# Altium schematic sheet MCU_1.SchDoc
size A4; PageSetup: Record=PageOptions|CenterHorizontal=True|CenterVertical=True|PrintScale=0.98|XCorrection=1.00|YCorrection=1.00|PrintKind=0|BorderSize=5000000|LeftOffset=0|BottomOffset=0|Orientation=2|PaperLength=1000|PaperWidth=1000|Scale=100|PaperSource=7|PrintQuality=-4|MediaType=1|DitherType=10|PaperKind=A4 210x297 ºÁÃ×|PrintScaleMode=1
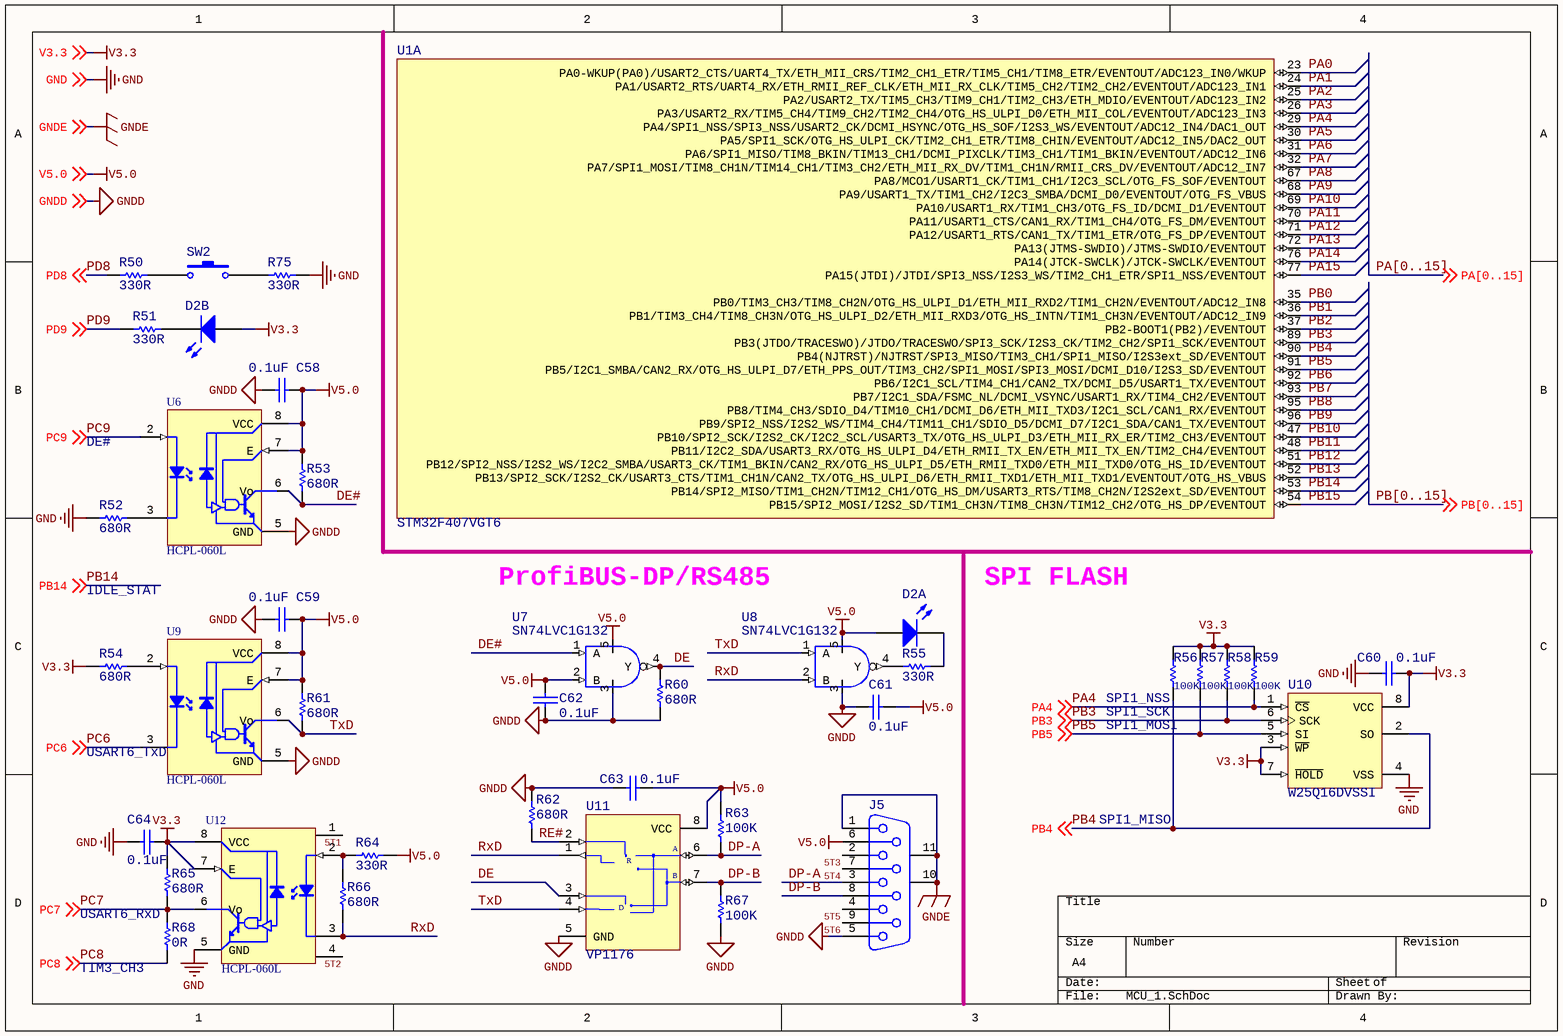
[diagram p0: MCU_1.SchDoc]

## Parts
C58  0.1uF  [C1608(0603)]
C59  0.1uF  [C1608(0603)]
C60  0.1uF  [C1608(0603)]
C61  0.1uF  [C1608(0603)]
C62  0.1uF  [C1608(0603)]
C63  0.1uF  [C1608(0603)]
C64  0.1uF  [C1608(0603)]
D2  LED-2  [LED-2]  (value not drawn)  (parts A,B of 2)
J5  D Connector 9  [DB9F]  (value not drawn)
R50  330R  [R1608(0603)]
R51  330R  [R1608(0603)]
R52  680R  [R1608(0603)]
R53  680R  [R1608(0603)]
R54  680R  [R1608(0603)]
R55  330R  [R1608(0603)]
R56  100K  [R1608(0603)]
R57  100K  [R1608(0603)]
R58  100K  [R1608(0603)]
R59  100K  [R1608(0603)]
R60  680R  [R1608(0603)]
R61  680R  [R1608(0603)]
R62  680R  [R1608(0603)]
R63  100K  [R1608(0603)]
R64  330R  [R1608(0603)]
R65  680R  [R1608(0603)]
R66  680R  [R1608(0603)]
R67  100K  [R1608(0603)]
R68  0R  [R1608(0603)]
R75  330R  [R1608(0603)]
SW2  SW-PB  [KEY 4.5x4.5x4.3mm]  (value not drawn)
U1  STM32F407VGT6  [TQFP100_N]  (part A of 5)
U6  HCPL-060L  [SO8_M]
U7  SN74LVC1G132  [SOT23-5_N]
U8  SN74LVC1G132  [SOT23-5_N]
U9  HCPL-060L  [SO8_M]
U10  W25Q16DVSSI  [SOIC8_M]
U11  VP1176  [SO8_M]
U12  HCPL-060L  [SO8_M]

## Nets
GND: C60.2 C64.2 R52.1 R75.2 U10.4(VSS) U12.5(GND) ; off-sheet GND
GNDD: C58.2 C59.2 C61.1 C62.2 C63.2 J5.5 R60.1 R62.2 R67.1 U6.5(GND) U7.3(GND) U8.3(GND) U9.5(GND) U11.5(GND) ; off-sheet GNDD
GNDE: J5.1 J5.10(MH1) J5.11(MH2) ; off-sheet GNDE
V3.3: C60.1 C64.1 D2.3(A2) R54.1 R56.2 R57.2 R58.2 R59.2 R65.2 U10.3(~{WP}) U10.7(~{HOLD}) U10.8(VCC) U12.7(E) U12.8(VCC) ; off-sheet V3.3
V5.0: C58.1 C59.1 C61.2 C62.1 C63.1 D2.1(A1) J5.6 R53.2 R61.2 R63.2 R64.2 U6.7(E) U6.8(VCC) U7.2(B) U7.5(VCC) U8.5(VCC) U9.7(E) U9.8(VCC) U11.8(VCC) ; off-sheet V5.0
5T1: U12.1
5T2: U12.4
5T3: J5.2
5T4: J5.7
5T5: J5.4
5T6: J5.9
DE: R60.2 U7.4(Y) U11.3(DE)
DE#: R53.1 U6.6(Vo) U7.1(A)
DP-A: J5.3 R63.1 U11.6(A)
DP-B: J5.8 R67.2 U11.7(B)
PA0: U1.23(PA0-WKUP(PA0)/USART2_CTS/UART4_TX/ETH_MII_CRS/TIM2_CH1_ETR/TIM5_CH1/TIM8_ETR/EVENTOUT/ADC123_IN0/WKUP)
PA1: U1.24(PA1/USART2_RTS/UART4_RX/ETH_RMII_REF_CLK/ETH_MII_RX_CLK/TIM5_CH2/TIM2_CH2/EVENTOUT/ADC123_IN1)
PA2: U1.25(PA2/USART2_TX/TIM5_CH3/TIM9_CH1/TIM2_CH3/ETH_MDIO/EVENTOUT/ADC123_IN2)
PA3: U1.26(PA3/USART2_RX/TIM5_CH4/TIM9_CH2/TIM2_CH4/OTG_HS_ULPI_D0/ETH_MII_COL/EVENTOUT/ADC123_IN3)
PA4: R59.1 U1.29(PA4/SPI1_NSS/SPI3_NSS/USART2_CK/DCMI_HSYNC/OTG_HS_SOF/I2S3_WS/EVENTOUT/ADC12_IN4/DAC1_OUT) U10.1(~{CS}) ; off-sheet PA4
PA5: U1.30(PA5/SPI1_SCK/OTG_HS_ULPI_CK/TIM2_CH1_ETR/TIM8_CHIN/EVENTOUT/ADC12_IN5/DAC2_OUT)
PA6: U1.31(PA6/SPI1_MISO/TIM8_BKIN/TIM13_CH1/DCMI_PIXCLK/TIM3_CH1/TIM1_BKIN/EVENTOUT/ADC12_IN6)
PA7: U1.32(PA7/SPI1_MOSI/TIM8_CH1N/TIM14_CH1/TIM3_CH2/ETH_MII_RX_DV/TIM1_CH1N/RMII_CRS_DV/EVENTOUT/ADC12_IN7)
PA8: U1.67(PA8/MCO1/USART1_CK/TIM1_CH1/I2C3_SCL/OTG_FS_SOF/EVENTOUT)
PA9: U1.68(PA9/USART1_TX/TIM1_CH2/I2C3_SMBA/DCMI_D0/EVENTOUT/OTG_FS_VBUS)
PA10: U1.69(PA10/USART1_RX/TIM1_CH3/OTG_FS_ID/DCMI_D1/EVENTOUT)
PA11: U1.70(PA11/USART1_CTS/CAN1_RX/TIM1_CH4/OTG_FS_DM/EVENTOUT)
PA12: U1.71(PA12/USART1_RTS/CAN1_TX/TIM1_ETR/OTG_FS_DP/EVENTOUT)
PA13: U1.72(PA13(JTMS-SWDIO)/JTMS-SWDIO/EVENTOUT)
PA14: U1.76(PA14(JTCK-SWCLK)/JTCK-SWCLK/EVENTOUT)
PA15: U1.77(PA15(JTDI)/JTDI/SPI3_NSS/I2S3_WS/TIM2_CH1_ETR/SPI1_NSS/EVENTOUT)
PB0: U1.35(PB0/TIM3_CH3/TIM8_CH2N/OTG_HS_ULPI_D1/ETH_MII_RXD2/TIM1_CH2N/EVENTOUT/ADC12_IN8)
PB1: U1.36(PB1/TIM3_CH4/TIM8_CH3N/OTG_HS_ULPI_D2/ETH_MII_RXD3/OTG_HS_INTN/TIM1_CH3N/EVENTOUT/ADC12_IN9)
PB2: U1.37(PB2-BOOT1(PB2)/EVENTOUT)
PB3: R58.1 U1.89(PB3(JTDO/TRACESWO)/JTDO/TRACESWO/SPI3_SCK/I2S3_CK/TIM2_CH2/SPI1_SCK/EVENTOUT) U10.6(SCK) ; off-sheet PB3
PB4: R56.1 U1.90(PB4(NJTRST)/NJTRST/SPI3_MISO/TIM3_CH1/SPI1_MISO/I2S3ext_SD/EVENTOUT) U10.2(SO) ; off-sheet PB4
PB5: R57.1 U1.91(PB5/I2C1_SMBA/CAN2_RX/OTG_HS_ULPI_D7/ETH_PPS_OUT/TIM3_CH2/SPI1_MOSI/SPI3_MOSI/DCMI_D10/I2S3_SD/EVENTOUT) U10.5(SI) ; off-sheet PB5
PB6: U1.92(PB6/I2C1_SCL/TIM4_CH1/CAN2_TX/DCMI_D5/USART1_TX/EVENTOUT)
PB7: U1.93(PB7/I2C1_SDA/FSMC_NL/DCMI_VSYNC/USART1_RX/TIM4_CH2/EVENTOUT)
PB8: U1.95(PB8/TIM4_CH3/SDIO_D4/TIM10_CH1/DCMI_D6/ETH_MII_TXD3/I2C1_SCL/CAN1_RX/EVENTOUT)
PB9: U1.96(PB9/SPI2_NSS/I2S2_WS/TIM4_CH4/TIM11_CH1/SDIO_D5/DCMI_D7/I2C1_SDA/CAN1_TX/EVENTOUT)
PB10: U1.47(PB10/SPI2_SCK/I2S2_CK/I2C2_SCL/USART3_TX/OTG_HS_ULPI_D3/ETH_MII_RX_ER/TIM2_CH3/EVENTOUT)
PB11: U1.48(PB11/I2C2_SDA/USART3_RX/OTG_HS_ULPI_D4/ETH_RMII_TX_EN/ETH_MII_TX_EN/TIM2_CH4/EVENTOUT)
PB12: U1.51(PB12/SPI2_NSS/I2S2_WS/I2C2_SMBA/USART3_CK/TIM1_BKIN/CAN2_RX/OTG_HS_ULPI_D5/ETH_RMII_TXD0/ETH_MII_TXD0/OTG_HS_ID/EVENTOUT)
PB13: U1.52(PB13/SPI2_SCK/I2S2_CK/USART3_CTS/TIM1_CH1N/CAN2_TX/OTG_HS_ULPI_D6/ETH_RMII_TXD1/ETH_MII_TXD1/EVENTOUT/OTG_HS_VBUS)
PB14: U1.53(PB14/SPI2_MISO/TIM1_CH2N/TIM12_CH1/OTG_HS_DM/USART3_RTS/TIM8_CH2N/I2S2ext_SD/EVENTOUT) ; off-sheet PB14
PB15: U1.54(PB15/SPI2_MOSI/I2S2_SD/TIM1_CH3N/TIM8_CH3N/TIM12_CH2/OTG_HS_DP/EVENTOUT)
PC6: U9.3(-) ; off-sheet PC6
PC7: R65.1 R68.2 U12.6(Vo) ; off-sheet PC7
PC8: R68.1 ; off-sheet PC8
PC9: U6.2(+) ; off-sheet PC9
PD8: R50.1 ; off-sheet PD8
PD9: R51.1 ; off-sheet PD9
RE#: R62.1 U11.2(~{RE})
RxD: R66.1 U8.2(B) U11.1(RO) U12.3(-)
TxD: R61.1 U8.1(A) U9.6(Vo) U11.4(DI)
NetD2_2: D2.2(K1) R55.2
NetD2_4: D2.4(K2) R51.2
NetR50_2: R50.2 SW2.1
NetR52_2: R52.2 U6.3(-)
NetR54_2: R54.2 U9.2(+)
NetR55_1: R55.1 U8.4(Y)
NetR64_1: R64.1 R66.2 U12.2(+)
NetR75_1: R75.1 SW2.2

Not connected (* = marked no-connect by the designer): U6 1 4; U9 1 4

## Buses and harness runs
bus PA[0..15]
bus PB[0..15]

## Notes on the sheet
- DE#
- IDLE_STAT
- ProfiBUS-DP/RS485
- SPI FLASH
- (near R56) SPI1_NSS
- (near R56) SPI1_SCK
- (near U9) USART6_TxD
- SPI1_MOSI
- SPI1_MISO
- USART6_RxD
- (near R68) TIM3_CH3

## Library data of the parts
C58-C64 = CAP: Capacitor
D2 = LED-2: Typical INFRARED GaAs LED
J5 = D Connector 9: Receptacle Assembly, 9 Position, Right Angle; PackageDocument: O; Positions: 9
R50-R68 R75 = Res Semi: Semiconductor Resistor; Value: 1K
SW2 = SW-PB: Switch
U1 = STM32F407VGT6: ARM Cortex-M4 32b MCU+FPU, 210DMIP, 1024 kB Flash, 192+4 kB RAM, Camera, 82 I/Os, 100-pin LQFP, -40 to +85°C, Tray; Internal RAM: 192kB; Operating Frequency (Processor Speed): 168MHz; A/D Converter: 16x12-bit; D/A Converter: 2x12-bit; 16-bit Timers (IC/OC/PWM): 12x16-bit(24/24/30); 32-bit Timer (IC/OC/PWM): 2x32-bit (8/8/8); Other Timer Functions: 2xWDG, RTC, 24-bit down counter; Serial Interface: 3xSPI/2xI2S/2xI2C/3xUSART(IrDa, ISO7816)/3xUART/2xUSB OTG FS/HS, 2xCAN/Ethernet MAC10/100, SDIO
U6 U9 U12 = HCPL-060
U10 = 25AA640A-I/SN: 64K SPI Bus Serial EEPROM, 8-Pin SOIC, Industrial Temperature
U11 = MAX485ESA: Low-Power, Slew-Rate-Limited RS-485/RS-422 Transceiver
